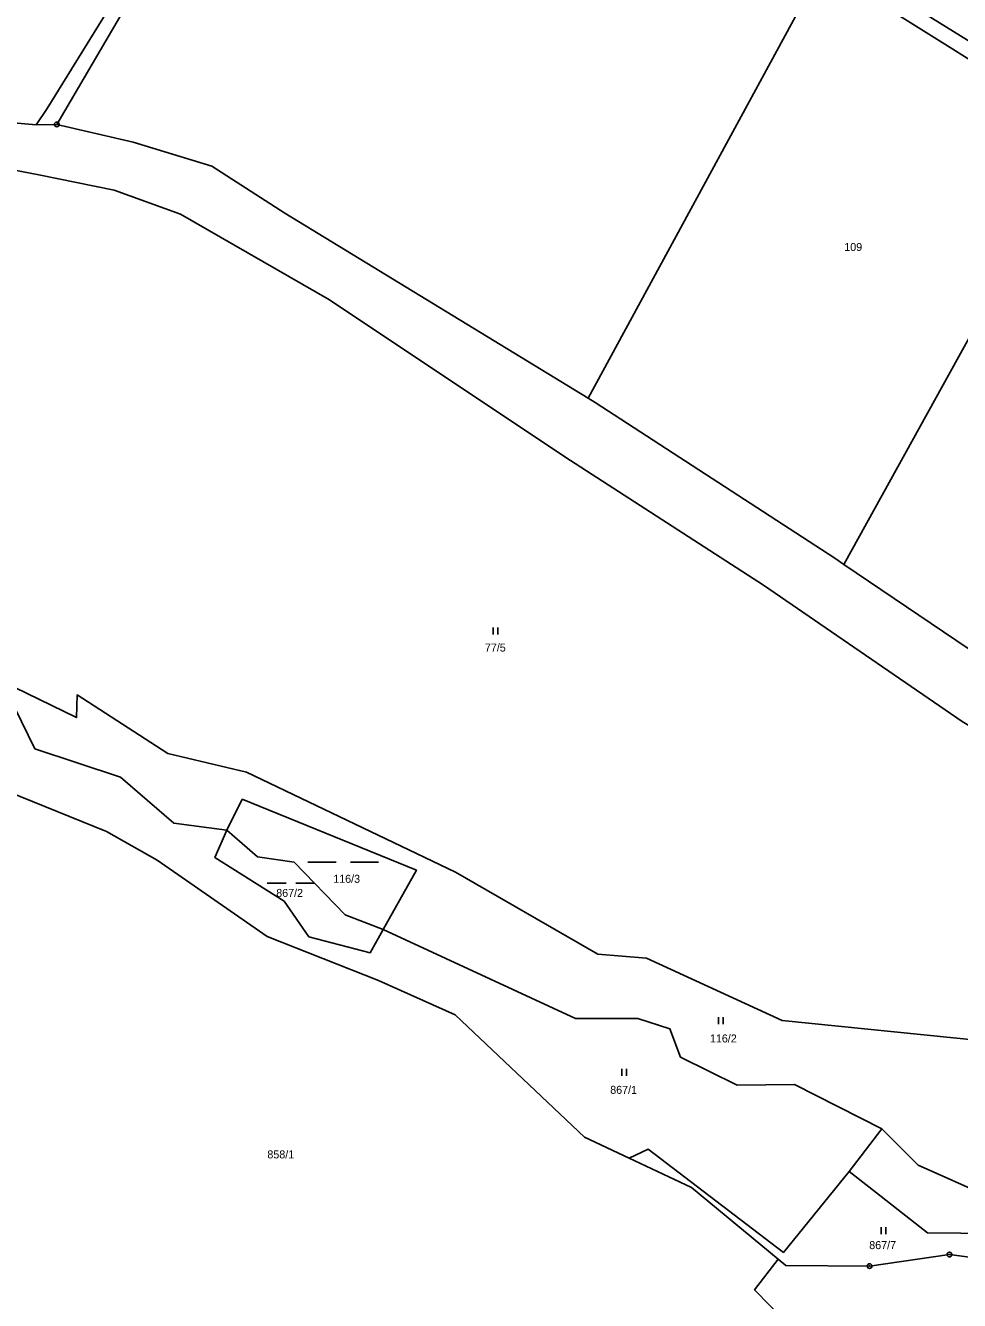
# Model space of a CAD drawing. Extents: x -680203 to -673936, y -1102717 to -1093650.
# Drawn here: x -679432.3 to -679233.9, y -1097210 to -1096939.2 of the extents above; entities that cross this region are included whole.
import ezdxf

# ---------------------------------------------------------------- set-up
doc = ezdxf.new("R2010")
doc.units = 0
for name, color, linetype in [('SOxx02xx_Koleje_param další_Popis10', 7, 'Continuous'), ('SOxxxxxx_Koleje_hlavní_body_Popis10', 7, 'Continuous'), ('SOxxxxxx_Osa_bod_P', 7, 'Continuous'), ('x_prac', 7, 'Continuous')]:
    doc.layers.add(name, color=color, linetype=linetype)

msp = doc.modelspace()

# ---------------------------------------------------------------- linework, layer by layer
at = {"layer": 'SOxx02xx_Koleje_param další_Popis10'}
for centre, radius in [((-679425.65, -1096960.24), 0.5), ((-679425.65, -1096960.24), 0.0303), ((-679236.05, -1097200.21), 0.5), ((-679236.05, -1097200.21), 0.0303), ((-679253.01, -1097202.65), 0.5), ((-679253.01, -1097202.65), 0.0303)]:
    msp.add_circle(centre, radius, dxfattribs=at)
at = {"layer": 'SOxxxxxx_Koleje_hlavní_body_Popis10'}
for p, q in [((-679332.94, -1097068.58), (-679332.94, -1097067.08)), ((-679331.94, -1097068.58), (-679331.94, -1097067.08)), ((-679372.3, -1097116.86), (-679366.3, -1097116.86)), ((-679363.3, -1097116.86), (-679357.3, -1097116.86)), ((-679380.94, -1097121.33), (-679376.92, -1097121.33)), ((-679374.91, -1097121.33), (-679370.89, -1097121.33)), ((-679285.12, -1097151.31), (-679285.12, -1097149.81)), ((-679284.12, -1097151.31), (-679284.12, -1097149.81)), ((-679305.66, -1097162.3), (-679305.66, -1097160.8)), ((-679304.66, -1097162.3), (-679304.66, -1097160.8)), ((-679250.56, -1097195.88), (-679250.56, -1097194.38)), ((-679249.56, -1097195.88), (-679249.56, -1097194.38))]:
    msp.add_line(p, q, dxfattribs=at)
at = {"layer": 'x_prac'}
for p, q in [((-679262.36, -1096923.61), (-679205.21, -1096959.16)), ((-679263.05, -1096926.86), (-679312.8, -1097018.4)), ((-679263.05, -1096926.86), (-679207.61, -1096961.69)), ((-679430.01, -1096960.36), (-679425.65, -1096960.24)), ((-679207.61, -1096961.69), (-679258.5, -1097053.66)), ((-679430.31, -1097092.8), (-679437.36, -1097078.47)), ((-679430.31, -1097092.8), (-679437.36, -1097078.47)), ((-679412.11, -1097098.84), (-679430.31, -1097092.8)), ((-679412.11, -1097098.84), (-679430.31, -1097092.8)), ((-679364.41, -1097128.1), (-679375.24, -1097116.87)), ((-679364.41, -1097128.1), (-679375.24, -1097116.87)), ((-679356.32, -1097131.19), (-679364.41, -1097128.1)), ((-679356.32, -1097131.19), (-679364.41, -1097128.1)), ((-679315.46, -1097150.07), (-679356.32, -1097131.19)), ((-679315.46, -1097150.07), (-679356.32, -1097131.19)), ((-679281.11, -1097164.24), (-679293.16, -1097158.31)), ((-679281.11, -1097164.24), (-679293.16, -1097158.31)), ((-679268.93, -1097164.09), (-679281.11, -1097164.24)), ((-679268.93, -1097164.09), (-679281.11, -1097164.24)), ((-679250.43, -1097173.52), (-679268.93, -1097164.09)), ((-679250.43, -1097173.52), (-679268.93, -1097164.09)), ((-679250.43, -1097173.52), (-679257.36, -1097182.6)), ((-679242.69, -1097181.26), (-679250.43, -1097173.52)), ((-679242.69, -1097181.26), (-679250.43, -1097173.52)), ((-679226.73, -1097188.33), (-679242.69, -1097181.26)), ((-679226.73, -1097188.33), (-679242.69, -1097181.26))]:
    msp.add_line(p, q, dxfattribs=at)
for points in [[(-679425.65, -1096960.24), (-679410.63, -1096934.64), (-679376.66, -1096875.96), (-679372.36, -1096869.27)], [(-679392.4, -1096897.07), (-679413.49, -1096933.81), (-679427.69, -1096956.87), (-679430.01, -1096960.36)], [(-679430.01, -1096960.36), (-679457.19, -1096957.92), (-679484.32, -1096955.44), (-679492.8, -1096951.8), (-679496.39, -1096949.53)], [(-679312.8, -1097018.4), (-679377.25, -1096979.08), (-679392.73, -1096969.09), (-679409.45, -1096964), (-679425.65, -1096960.24)], [(-679435, -1096969.9), (-679429.44, -1096970.97), (-679413.47, -1096974.22), (-679399.4, -1096979.29), (-679367.76, -1096997.52), (-679317.75, -1097030.81), (-679275.55, -1097058.08), (-679233.35, -1097087.01), (-679223.54, -1097092.89), (-679204.77, -1097105.11)], [(-679258.5, -1097053.66), (-679260.42, -1097052.36), (-679311.31, -1097019.31), (-679312.8, -1097018.4)], [(-679204.08, -1097089.81), (-679221.41, -1097078.71), (-679258.5, -1097053.66)], [(-679216.77, -1097150.67), (-679220.32, -1097148.71), (-679229.59, -1097154.73), (-679271.6, -1097150.53), (-679300.43, -1097137.27), (-679310.71, -1097136.4), (-679340.95, -1097119.03), (-679385.34, -1097097.78), (-679402.06, -1097093.85), (-679421.34, -1097081.39), (-679421.46, -1097086.19), (-679437.36, -1097078.47)], [(-679304.05, -1097179.76), (-679313.56, -1097175.27), (-679341.04, -1097149.31), (-679357.29, -1097142.04), (-679380.96, -1097132.65), (-679404.36, -1097116.44), (-679415.1, -1097110.36), (-679451.86, -1097095.51)], [(-679389.52, -1097110.13), (-679400.82, -1097108.6), (-679412.11, -1097098.84)], [(-679389.52, -1097110.13), (-679400.82, -1097108.6), (-679412.11, -1097098.84)], [(-679389.52, -1097110.13), (-679386.25, -1097103.53), (-679349.28, -1097118.61), (-679356.32, -1097131.19)], [(-679356.32, -1097131.19), (-679359.11, -1097136.16), (-679372.11, -1097132.74), (-679377.34, -1097125.2), (-679392.11, -1097115.9), (-679389.52, -1097110.13)], [(-679375.24, -1097116.87), (-679383.05, -1097115.76), (-679389.52, -1097110.13)], [(-679375.24, -1097116.87), (-679383.05, -1097115.76), (-679389.52, -1097110.13)], [(-679293.16, -1097158.31), (-679295.46, -1097152.27), (-679302.25, -1097150.07), (-679315.46, -1097150.07)], [(-679293.16, -1097158.31), (-679295.46, -1097152.27), (-679302.25, -1097150.07), (-679315.46, -1097150.07)], [(-679304.05, -1097179.76), (-679300.05, -1097177.86), (-679271.33, -1097199.76), (-679257.36, -1097182.6)], [(-679272.42, -1097201.19), (-679290.83, -1097185.99), (-679304.05, -1097179.76)], [(-679257.36, -1097182.6), (-679253.16, -1097185.83), (-679240.73, -1097195.57), (-679219.49, -1097195.78), (-679210.23, -1097203.67)], [(-679214.4, -1097203.11), (-679236.05, -1097200.21), (-679253.01, -1097202.65), (-679270.81, -1097202.53), (-679272.42, -1097201.19)], [(-679251.36, -1097234.37), (-679277.44, -1097207.72), (-679272.42, -1097201.19)]]:
    msp.add_lwpolyline(points, dxfattribs=at)

# ---------------------------------------------------------------- texts
at = {"layer": 'SOxxxxxx_Osa_bod_P'}
for s, p in [('109', (-679258.38, -1096987.12)), ('77/5', (-679334.72, -1097072.18)), ('116/3', (-679366.93, -1097121.28)), ('867/2', (-679379.04, -1097124.28)), ('116/2', (-679286.92, -1097155.18)), ('867/1', (-679308.1, -1097166.09)), ('858/1', (-679380.92, -1097179.8)), ('867/7', (-679253.08, -1097199.06))]:
    msp.add_text(s, height=1.7, dxfattribs=at).set_placement(p)

doc.saveas('drawing.dxf')
